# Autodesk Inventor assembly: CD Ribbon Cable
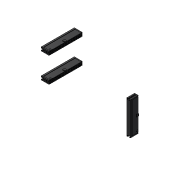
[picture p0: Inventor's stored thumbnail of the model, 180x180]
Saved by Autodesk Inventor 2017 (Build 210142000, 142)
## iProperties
Created: 2007-02
Part Number: CD Ribbon Cable
Document SubType Name: Assembly
Designer: DanielSeverino
Author: DanielSeverino
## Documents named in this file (2)
- C:\Users\DanielSeverino\Desktop\01\CD Ribbon Cable.iam
- C:\Users\DanielSeverino\Desktop\01\Ribbon Cable Connector.ipt
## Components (3 placed, 1 different names)
1. Ribbon Cable Connector:1
2. Ribbon Cable Connector:2
3. Ribbon Cable Connector:3
